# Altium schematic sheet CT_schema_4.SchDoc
size 461 x 327 mm
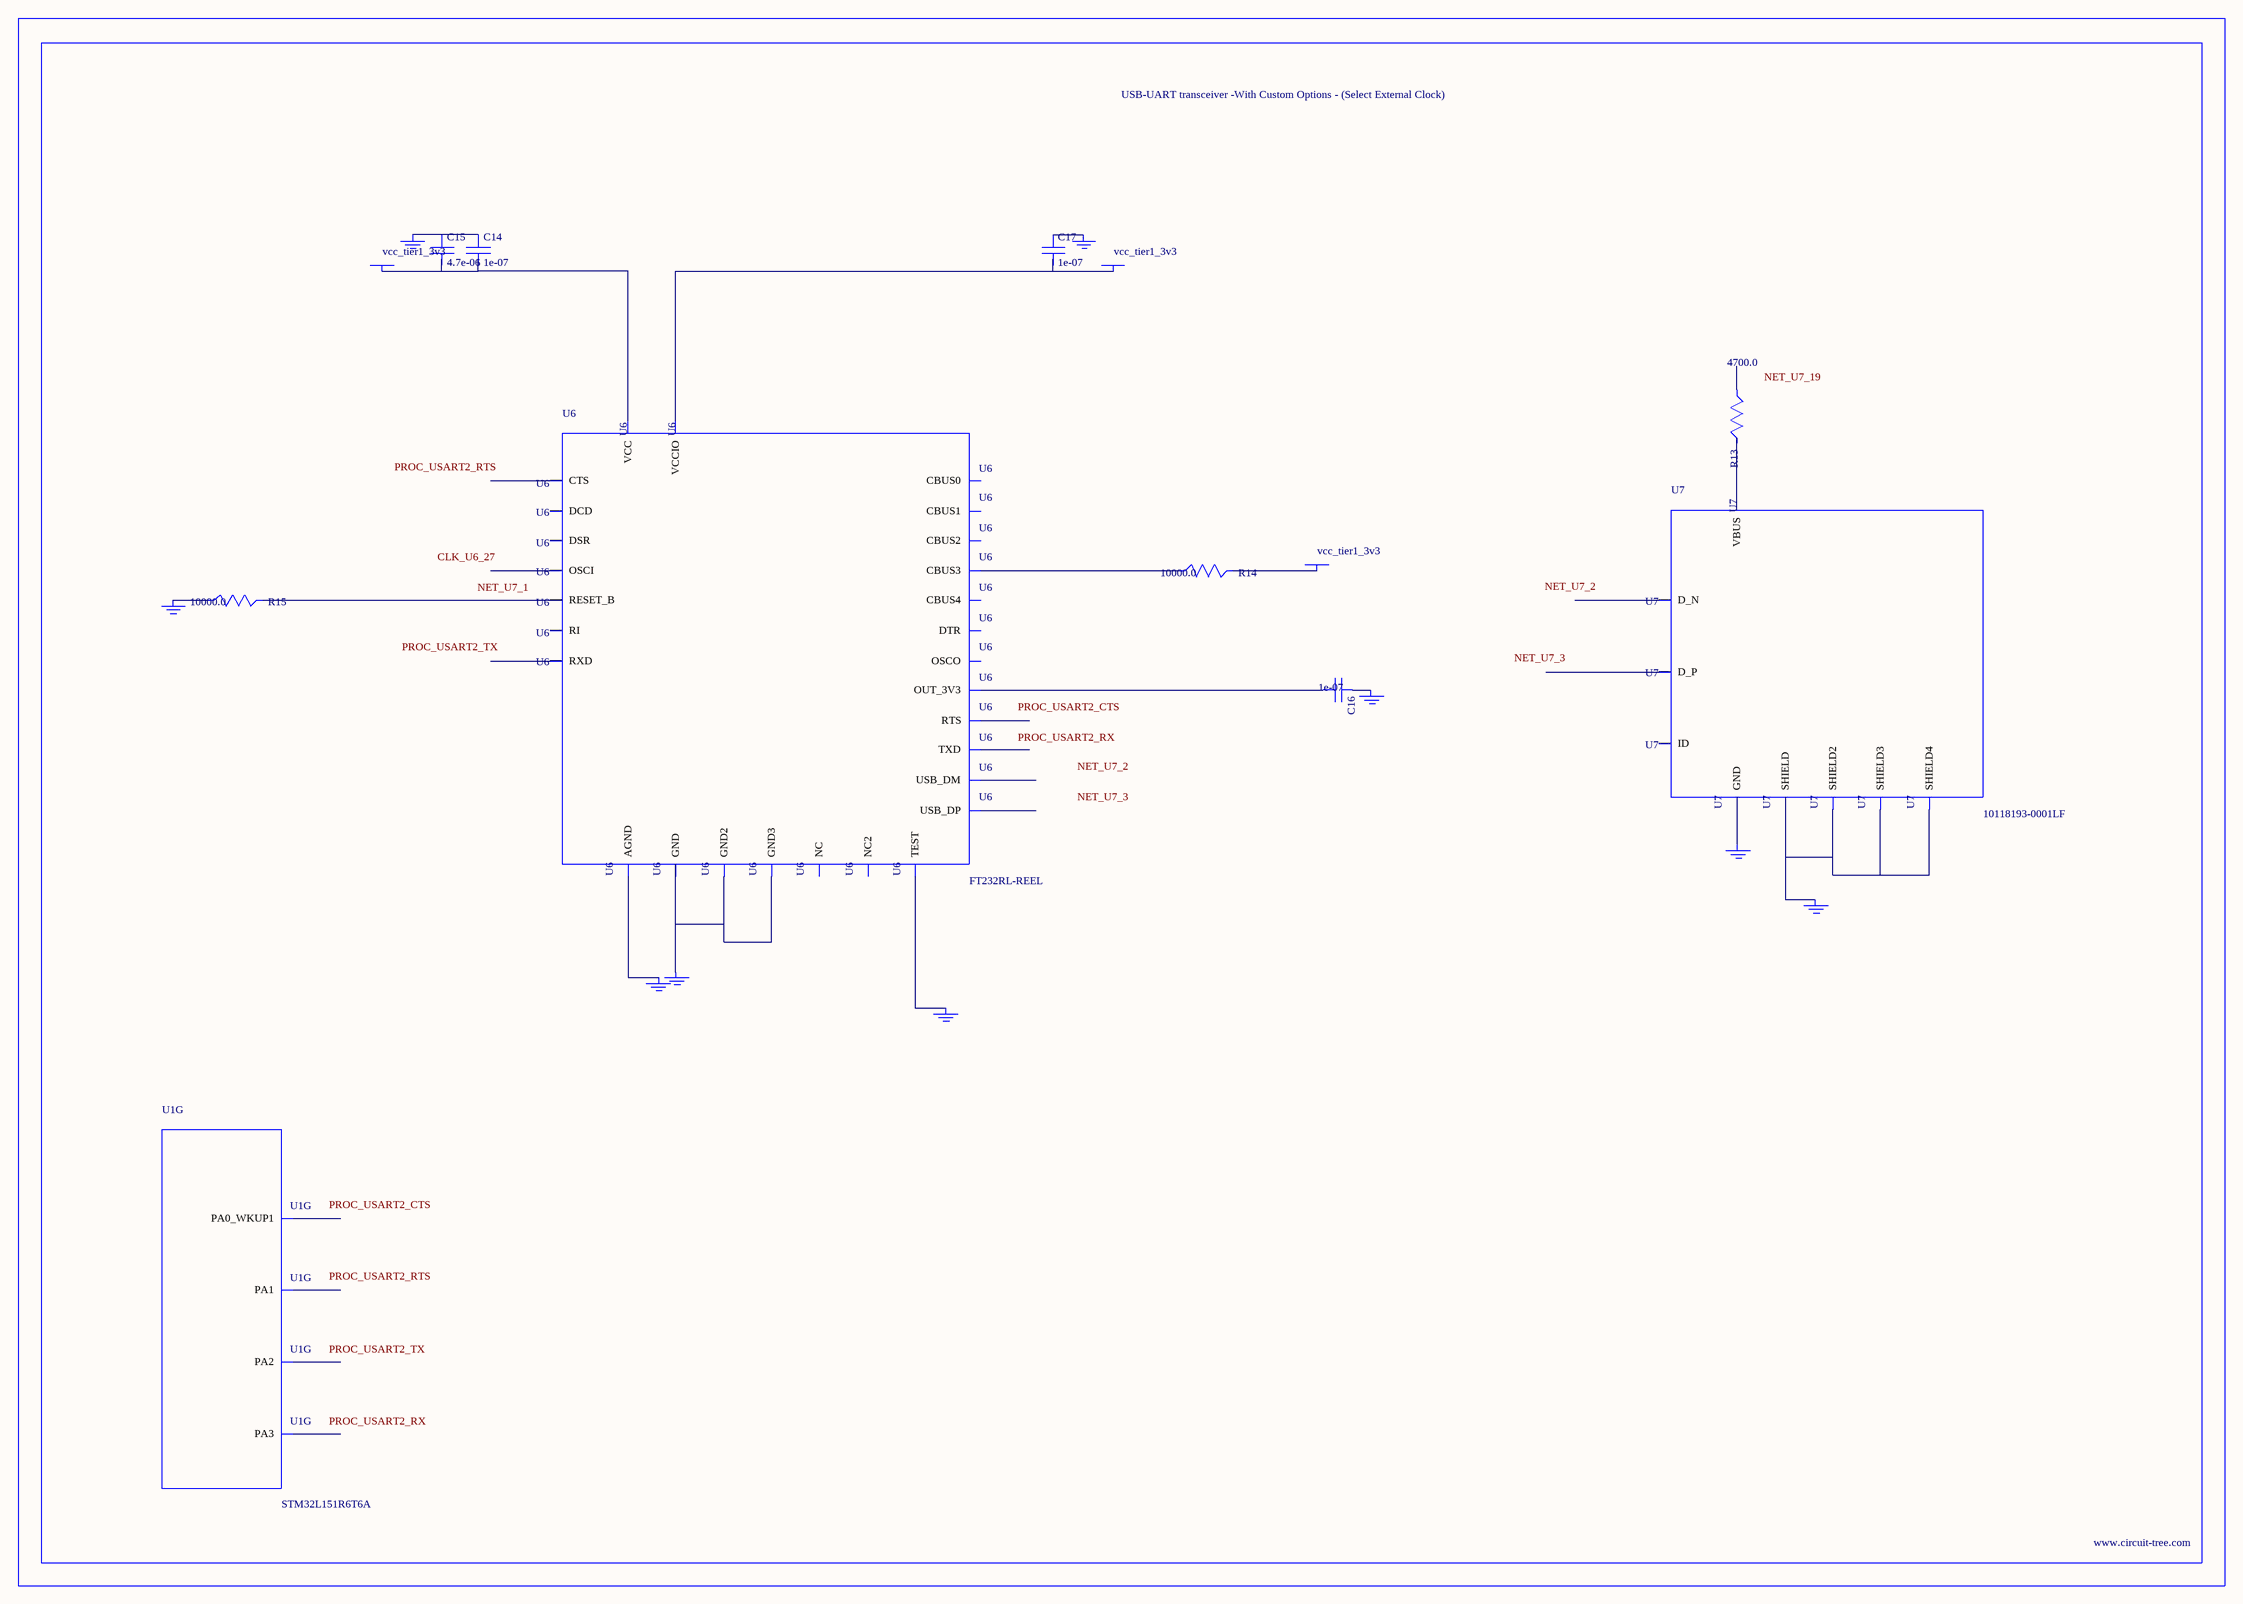
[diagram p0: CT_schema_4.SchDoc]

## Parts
BORDER3  (no value)
C14  1e-07  [C0402]
C15  4.7e-06  [C0805]
C16  1e-07  [C0402]
C17  1e-07  [C0402]
GND_INSTANCE_3_0  (no value)
GND_INSTANCE_3_1  (no value)
GND_INSTANCE_3_2  (no value)
GND_INSTANCE_3_3  (no value)
GND_INSTANCE_3_4  (no value)
GND_INSTANCE_3_5  (no value)
GND_INSTANCE_3_6  (no value)
GND_INSTANCE_3_7  (no value)
GND_INSTANCE_3_8  (no value)
POWER_INSTANCE_3_0  vcc_tier1_3v3
POWER_INSTANCE_3_1  vcc_tier1_3v3
POWER_INSTANCE_3_2  vcc_tier1_3v3
R13  4700.0  [R0603]
R14  10000.0  [R0603]
R15  10000.0  [R0603]
U1  STM32L151R6T6A  [LQFP64]  (part G of 7)
U6  FT232RL-REEL  [SSOP-28]
U7  10118193-0001LF  [FCI_10118193-0001LF]

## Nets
NetC14_1: C14.1 C15.1 GND_INSTANCE_3_3.0(GND)
NetC14_2: C14.2 C15.2 POWER_INSTANCE_3_2.0(PWR) U6.20(VCC)
NetC16_1: C16.1 GND_INSTANCE_3_1.0(GND)
NetC16_2: C16.2 U6.17(OUT_3V3)
NetC17_1: C17.1 GND_INSTANCE_3_0.0(GND)
NetC17_2: C17.2 POWER_INSTANCE_3_0.0(PWR) U6.4(VCCIO)
NetGND_INSTANCE_3_2_0: GND_INSTANCE_3_2.0(GND) R15.1
NetGND_INSTANCE_3_4_0: GND_INSTANCE_3_4.0(GND) U6.25(AGND)
NetGND_INSTANCE_3_5_0: GND_INSTANCE_3_5.0(GND) U6.26(TEST)
NetGND_INSTANCE_3_6_0: GND_INSTANCE_3_6.0(GND) U6.7(GND) U6.18(GND2) U6.21(GND3)
NetGND_INSTANCE_3_7_0: GND_INSTANCE_3_7.0(GND) U7.6(SHIELD) U7.7(SHIELD2) U7.8(SHIELD3) U7.9(SHIELD4)
NetGND_INSTANCE_3_8_0: GND_INSTANCE_3_8.0(GND) U7.5(GND)
NetPOWER_INSTANCE_3_1_0: POWER_INSTANCE_3_1.0(PWR) R14.2
NetR13_2: R13.2 U7.1(VBUS)
NetR14_1: R14.1 U6.14(CBUS3)
NetR15_2: R15.2 U6.19(RESET_B)

Not connected (* = marked no-connect by the designer): R13 1; U1 14(PA0_WKUP1) 15(PA1) 16(PA2) 17(PA3); U6 1(TXD) 2(DTR) 3(RTS) 5(RXD) 6(RI) 8(NC) 9(DSR) 10(DCD) 11(CTS) 12(CBUS4) 13(CBUS2) 15(USB_DP) 16(USB_DM) 22(CBUS1) 23(CBUS0) 24(NC2) 27(OSCI) 28(OSCO); U7 2(D_N) 3(D_P) 4(ID)

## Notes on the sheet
- Labels drawn without touching a wire or pin: CLK_U6_27, NET_U7_1, NET_U7_2, NET_U7_3, NET_U7_19, PROC_USART2_CTS, PROC_USART2_RTS, PROC_USART2_RX, PROC_USART2_TX

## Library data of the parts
BORDER3 = BORDER_PAGE3
C14 C16 C17 = C0402C104K3RACTU
C15 = C0805C475K4RACTU
GND_INSTANCE_3_0-GND_INSTANCE_3_8 = GND
POWER_INSTANCE_3_0-POWER_INSTANCE_3_2 = PWR
R13 = RC0603JR-074K7L
R14 R15 = RC0603JR-0710KL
